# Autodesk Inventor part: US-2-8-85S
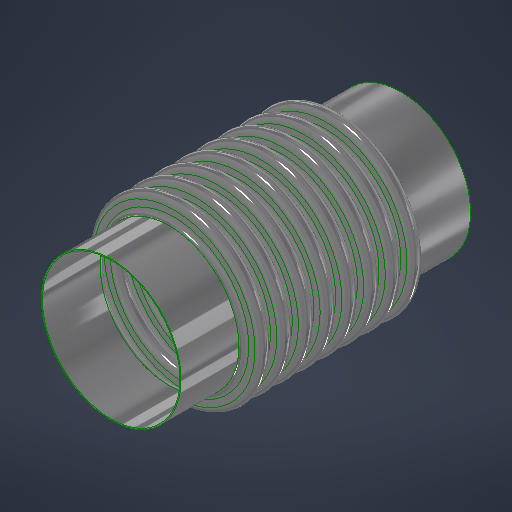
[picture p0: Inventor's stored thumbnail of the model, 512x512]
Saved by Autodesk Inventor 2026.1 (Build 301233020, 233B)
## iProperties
Created: 2026-07
Part Number: US-2-8-85S
Project: =STOCK BELLOWS: <Stock Number><SFILL>
Material: ASTM A240-304
Description: =STOCK BELLOWS: <Stock Number>, <SID_> I.D., <SOD_> O.D., <SPLY_> PLY, <Category>, <SNET_CONS> CONS.<PITCH_><STANGENT_> TANGENT<SFILL>
Document SubType Name: Sheet Metal
Designer: LC
Stock Number: U.S-2-8-85S
Surface Area: 659.127 cm^2
Volume: 56.61 cm^3
Sheet Metal Rule: Default
Appearance: STAINLESS STEEL
Category: 26 GA (0.018 THICK)
RuleStatus: InUse
Author: LC
Keywords: 20 GA (0.036 THICK)
NET_TUBE: 3.428
COUNTER: 1.500
PBAR: 1.214
PSET: 5.356
PLY: 2
CONS: 2
THK: 0.036
ID: 4.500
OD: 5.500
CONS_: 2
TANGENT: 0.500
PITCH: 0.375
BELLOWS_UPSET: 0.000
NET_CONS: 2
S_CONS: 0
Description_Units: 0
ID_M: 114.30 mm
OD_M: 139.70 mm
THK_M: 0.91 mm
ID_U: 4.500 in
OD_U: 5.500 in
THK_U: 0.036 in
TANGENT2: 0.500
d79: 1.000
d82: 1.000
d83: 26.000
d84: 24.000
d80: 2.571
d81: 10
SID: 2.375
SCONS_: 8
SPITCH: 0.250
SBELLOWS_UPSET: 0.000
SNET_CONS: 8
SS_CONS: 0
SCONS: 8
d174: 8
d177: 0.018
d178: 2.375
d179: 3.000
d180: 0.375
d181: 1.000
d182: 0.000
d190: 8
d191: 1
d192: 1
d193: 8
d194: 0
PART_NUMBER: U.S-2-8-85S
PRESSURE: 85
SIZE: 2.00
STANGENT_: 1.000
d214: 8
d217: 0.030
d218: 6.625
d219: 8.125
d220: 0.500
d221: 1.000
d222: 0.000
d230: 8
d231: 1
d232: 1
d233: 8
d234: 0
STANGENT: 4.000
SPLY_: 1
STHK_: 0.018
SID_: 2.375
SOD_: 3.000
SPITCH_: 0.375
STANGENT__: 1.000
SBELLOWS_UPSET_: 0.000
SDIFF_TAN: 1.000
TAN_TO_TAN: 0.750 in
d252: 2
d275: 2
d287: 0.050
d289: 0.500
d290: 0.000
d263: 2
d265: 1
d268: 2
d269: 0
d286: 2
d288: 1
d291: 2
d292: 0
SOD_NECK: 2 7/16
CFILL: .
SFILL: .
PITCH_: =, <SPITCH_> PITCH,
SREROLL: 0.750
MATTABLE: 20 GA (0.036 THICK)
MESH: ,
CSECT: 2
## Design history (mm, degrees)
sketch "Sketch2"
  geometry: L1 (0, -183.595)-(0, 600.956) reference; L2 (58.979, 0)-(57.15, 0); L3 (60.446, -1.467)-(66.554, -1.467); L4 (60.446, -3.296)-(66.554, -3.296); L5 (66.554, -8.058)-(60.446, -8.058); L6 (66.554, -6.229)-(60.446, -6.229); L7 (58.979, -9.525)-(57.15, -9.525); L8 (60.446, 0)-(60.446, -9.525); L9 (66.554, -4.762)-(69.85, -4.763); L10 (57.15, 0)-(57.15, -9.525); L11 (20.376, 102.841)-(20.376, 101.926); L12 (58.262, 488.877)-(58.262, 349.177); L13 (58.262, 479.352)-(58.262, 339.652); L14 (93.133, -58.817)-(93.133, -71.517); L15 (118.746, -66.401)-(118.746, -66.401); L16 (66.554, -6.229)-(66.554, -8.058); L17 (60.446, -6.229)-(60.446, -8.058); L18 (60.446, -7.144)-(66.554, -7.144); L19 (69.85, 0)-(69.85, -9.525); L20 (-66.554, -6.229)-(-66.554, -8.058); L21 (-66.554, -1.467)-(-60.446, -1.467); L22 (-66.554, -3.296)-(-60.446, -3.296); L23 (-60.446, -6.229)-(-66.554, -6.229); L24 (-66.554, -7.144)-(-60.446, -7.144); L25 (-60.446, -8.058)-(-66.554, -8.058); L26 (-60.446, -6.229)-(-60.446, -8.058); L27 (-57.15, -2.522)-(-57.15, -12.047); L28 (-60.446, -4.763)-(-57.15, -4.763); L29 (-66.554, 3.828)-(-66.554, -9.525); L30 (-68.021, 0)-(-69.85, 0); L31 (-69.85, 0)-(-69.85, -9.525); L32 (-68.021, -9.525)-(-69.85, -9.525); A1 r 1.467 centre (60.446, 0) between (58.979, 0) and (60.446, -1.467); A2 r 3.296 centre (60.446, 0) between (57.15, 0) and (60.446, -3.296); A3 r 3.296 centre (66.554, -4.762) between (66.554, -8.058) and (66.554, -1.467); A4 r 1.467 centre (66.554, -4.762) between (66.554, -6.229) and (66.554, -3.296); A5 r 1.467 centre (60.446, -9.525) between (60.446, -8.058) and (58.979, -9.525); A6 r 3.296 centre (60.446, -9.525) between (60.446, -6.229) and (57.15, -9.525); A7 r 2.381 centre (66.554, -4.762) between (66.554, -7.144) and (68.936, -4.762); A8 r 2.381 centre (60.446, -9.525) between (60.446, -7.144) and (58.064, -9.525); A9 r 1.467 centre (-66.554, -9.525) between (-66.554, -8.058) and (-68.021, -9.525); A10 r 1.467 centre (-60.446, -4.763) between (-60.446, -6.229) and (-60.446, -3.296); A11 r 2.381 centre (-60.446, -4.763) between (-60.446, -7.144) and (-58.064, -4.763); A12 r 3.296 centre (-60.446, -4.763) between (-60.446, -8.058) and (-60.446, -1.467); A13 r 2.381 centre (-66.554, -9.525) between (-66.554, -7.144) and (-68.936, -9.525); A14 r 3.296 centre (-66.554, -9.525) between (-66.554, -6.229) and (-69.85, -9.525); A15 r 1.467 centre (-66.554, 0) between (-68.021, 0) and (-66.554, -1.467); A16 r 3.296 centre (-66.554, 0) between (-69.85, 0) and (-66.554, -3.296); 10 further points
  constraints: 62 end point, 38 point on circle, 20 tangent, 16 centre point, 12 parallel, 9 midpoint, 7 vertical, 6 coincident, 6 concentric, 6 point on line, 4 equal radius, 4 perpendicular, 3 horizontal, 1 collinear, 1 horizontal alignment, 10 other
  dimensions: "THK" = 0.9144 distance of L11.start L11.end; "ID" = 114.3 distance of L11.end point (20.376, -12.374); "OD" = 139.7 distance of L12.start L12.end; "PITCH" = 9.525 distance of L12.start L13.start; "TANGENT" = 12.7 distance of L14.start L14.end; "BELLOWS_UPSET" = 0 distance of L15.start L15.end; "d43" = 114.3 diameter of L10 L1 (= ID); "d44" = 139.7 diameter of L9.end L1 (= OD); "d45" = 1.8288 distance between parallel lines of L5 L6 (computed from THK, PLY); "d46" = 3.29565 radius of A3 (computed from PITCH, THK, PLY); "UPSET_PITCH" = 9.525 distance of L2.end L7.end (derived); "SIDEWALL_ANGLE" = 0 deg angle of L3 L9 (derived); "CON_GAP" = 2.9337 distance of point (60.446, -6.229) point (60.446, -3.296) (derived); "TAN1" = 3.74046 dimension on A8 (derived); "TAN2" = 3.74046 dimension on A7 (derived); "LEG1" = 6.1087 distance of L18.start L18.end (derived); "d278" = 1.8288 distance between parallel lines of L25 L23 (derived); "d279" = 3.29565 radius of A12 (derived); "d280" = 9.525 distance of L30.end L31.end (derived); "d281" = 360 deg dimension on L21 L28 (derived); "d282" = 2.9337 distance of point (-66.554, -6.229) point (-66.554, -3.296) (derived); "d283" = 3.74046 dimension on A13 (derived); "d284" = 3.74046 dimension on A11 (derived); "d285" = 6.1087 distance of L24.start L24.end (derived); "d293" = 114.3 diameter of L27 L1 (derived); "d294" = 139.7 diameter of L31 L1 (derived)
  node "Sketch Rectangular Pattern1" dims "d31" = 25.4, "ID" = 114.3
  node "Sketch Rectangular Pattern2" dims "d39" = 25.4, "PITCH" = 9.525
revolve "CONS" stored, may be unused: angle "d48" = 90 deg
node "BELLOW MIDPLANE"
pattern_linear "Rectangular Pattern2" dims "d52" = 9.525 (= UPSET_PITCH)
sketch "Sketch5"
  geometry: C1 r 58.979 at (0, 0) reference; C2 r 57.15 at (0, 0) reference
extrude "TANGENT" new body sketch "Sketch5" distance "d53" = 12.7 (= TANGENT); taper "d54" = 0 deg
revolve "SAMETAN" stored, may be unused: angle "d65" = 90 deg
revolve "DIFFTAN" stored, may be unused: angle "d70" = 90 deg
sketch "Sketch9"
  geometry: L1 (58.391, 0)-(-58.391, 0) reference; L2 (0, -17.78)-(0, 17.78) reference; L3 (41.708, 0)-(-41.708, 0); L4 (41.708, -11.906)-(41.708, 11.906); L5 (29.008, -11.906)-(29.008, 11.906); L6 (15.418, 11.906)-(15.418, -11.906); L7 (-29.008, -11.906)-(-29.008, 11.906); L8 (-41.708, -11.906)-(-41.708, 11.906); L9 (40.914, -11.906)-(40.914, 11.906); L10 (41.708, -11.906)-(40.914, -11.906); L11 (41.708, 11.906)-(40.914, 11.906); L12 (15.815, 11.906)-(15.022, 11.906); L13 (15.022, 11.906)-(15.022, -11.906); L14 (15.022, -11.906)-(15.815, -11.906); L15 (15.815, -11.906)-(15.815, 11.906); L16 (-15.815, 11.906)-(-15.815, -11.906); L17 (-15.418, 11.906)-(-15.418, -11.906); L18 (-15.815, -11.906)-(-15.022, -11.906); L19 (-15.022, -11.906)-(-15.022, 11.906); L20 (-15.022, 11.906)-(-15.815, 11.906); L21 (-41.708, -11.906)-(-40.914, -11.906); L22 (-40.914, -11.906)-(-40.914, 11.906); L23 (-40.914, 11.906)-(-41.708, 11.906); L24 (-41.708, 11.906)-(-41.708, -11.906); L25 (41.708, -0.397)-(-41.708, -0.397); L26 (-41.708, -0.397)-(-41.708, 0.397); L27 (-41.708, 0.397)-(41.708, 0.397); L28 (41.708, 0.397)-(41.708, -0.397); L29 (-41.708, 11.906)-(41.708, 11.906); L30 (41.708, 11.906)-(41.708, 12.7); L31 (41.708, 12.7)-(-41.708, 12.7); L32 (-41.708, 12.7)-(-41.708, 11.906); L33 (41.708, -11.906)-(-41.708, -11.906); L34 (-41.708, -11.906)-(-41.708, -12.7); L35 (-41.708, -12.7)-(41.708, -12.7); L36 (41.708, -12.7)-(41.708, -11.906); 30 further points
  constraints: 68 end point, 13 midpoint, 13 parallel, 8 horizontal, 7 perpendicular, 6 equal length, 3 point on line, 2 vertical, 14 other
  dimensions: "d115" = 23.8125 distance of L4.start L4.end (derived); "d116" = 12.7 distance between parallel lines of L4 L5 (derived); "d117" = 13.58962 distance between parallel lines of L5 L6 (derived); "d125" = 44.42645 distance between parallel lines of L7 L6 (derived); "d127" = 12.7 distance between parallel lines of L8 L7 (derived); "d128" = 26.28962 distance between parallel lines of L6 L4 (derived); "d130" = 83.41607 distance between parallel lines of L8 L4 (derived); "RULER_THK" = 0.79375 distance between parallel lines of L4 L9; "d135" = 0.79375 distance of L13.end L14.end (derived); "d138" = 30.83684 distance of L13.end L16.end (derived); "d143" = 0.79375 distance of L22.end L8.end (derived); "d144" = 0.79375 distance between parallel lines of L27 L25 (derived)
extrude "RULER" join sketch "Sketch9" distance "d149" = 0.79375 (derived); taper "d150" = 0 deg
extrude "BARS" join sketch "Sketch9" distance "d151" = 0.79375 (derived); taper "d152" = 0 deg
pattern_linear "Rectangular Pattern4" dims "d155" = 30.83684 (derived)
sketch "Sketch13"
  geometry: L1 (93.149, -52.467)-(93.149, -77.867); L2 (30.62, 0)-(30.162, 0); L3 (30.62, -9.525)-(30.162, -9.525); L4 (35.49, -7.372)-(32.772, -7.372); L5 (35.49, -6.915)-(32.772, -6.915); L6 (35.49, -4.763)-(38.1, -4.763); L7 (32.772, -2.153)-(35.49, -2.153); L8 (32.772, 0)-(32.772, -9.525); L9 (30.162, 0)-(30.162, -9.525); L10 (58.254, -373.664)-(58.254, -449.864); L11 (58.254, -383.189)-(58.254, -459.389); L12 (58.254, -402.239)-(58.254, -478.439); L13 (58.254, -411.764)-(58.254, -487.964); L14 (58.254, -421.289)-(58.254, -497.489); L15 (58.254, -430.814)-(58.254, -507.014); L16 (58.254, -440.339)-(58.254, -516.539); L17 (58.254, -392.714)-(58.254, -468.914); L18 (20.376, 102.383)-(20.376, 101.926); L19 (32.772, -2.61)-(35.49, -2.61); L20 (0, -696.265)-(0, 235.847) reference; L21 (-23.752, 0)-(142.514, 0) reference; A1 r 2.153 centre (32.772, 0) between (30.62, 0) and (32.772, -2.153); A2 r 2.153 centre (32.772, -9.525) between (32.772, -7.372) and (30.62, -9.525); A3 r 2.61 centre (32.772, -9.525) between (32.772, -6.915) and (30.162, -9.525); A4 r 2.153 centre (35.49, -4.763) between (35.49, -6.915) and (35.49, -2.61); A5 r 2.61 centre (35.49, -4.763) between (35.49, -7.372) and (35.49, -2.153); A6 r 2.61 centre (32.772, 0) between (30.162, 0) and (32.772, -2.61); 6 further points; 1 other entity
  constraints: 38 end point, 15 point on circle, 9 tangent, 6 centre point, 6 parallel, 5 vertical alignment, 4 point on line, 4 vertical, 3 coincident, 3 concentric, 2 collinear, 2 equal radius, 1 horizontal, 1 perpendicular, 23 other
  dimensions: "SBELLOWS_UPSET_" = 0 distance of point (118.762, -66.401) point (118.762, -66.401); "STOTAL_THK_BELLOW__" = 0.4572 distance between parallel lines of L4 L5 (derived); "d224" = 2.60985 radius of A5 (derived); "d225" = 9.525 distance of L2.end L3.end (derived); "SSIDEWALL_ANGLE_" = 360 deg dimension on L7 L6 (derived); "SSCON_GAP_" = 4.3053 distance of point (32.772, -6.915) point (32.772, -2.61) (derived); "d235" = 60.325 diameter of L9 L20 (derived); "d236" = 76.2 diameter of L6.end L20 (derived)
  node "Sketch Rectangular Pattern4" dims "d228" = 25.4
  node "Sketch Rectangular Pattern5" dims "d229" = 25.4
revolve "SBELLOW" stored, may be unused: angle "d197" = 90 deg
pattern_linear "Rectangular Pattern5" dims "d204" = 9.525 (derived)
revolve "STANGENT" stored, may be unused: angle "d240" = 90 deg
revolve "SSAMETAN" stored, may be unused: angle "d241" = 90 deg
revolve "SDIFFTAN" stored, may be unused: angle "d246" = 90 deg
revolve "INVCON" stored, may be unused: angle "d295" = 90 deg
pattern_linear "Rectangular Pattern6" dims "d298" = 9.525 (derived)
revolve "INVTANGENT" stored, may be unused: angle "d302" = 90 deg
revolve "INVSAMETAN" stored, may be unused: angle "d307" = 90 deg
revolve "INVDIFFTAN" stored, may be unused: angle "d312" = 90 deg
sketch "ID BELLOW MOUNT CALC"
  geometry: L1 (44.45, 0)-(38.1, 0); L2 (38.1, 0)-(38.1, 12.7); L3 (38.1, 12.7)-(44.45, 12.7); L4 (44.45, 12.7)-(44.45, 0); L5 (36.513, 12.7)-(34.684, 12.7); L6 (34.684, 12.7)-(34.684, 0); L7 (34.684, 0)-(36.513, 0); L8 (36.513, 0)-(36.513, 12.7); L9 (0, -2.54)-(0, 15.24) reference; L10 (-8.89, 0)-(53.34, 0) reference; 1 further point
  constraints: 16 end point, 5 parallel, 2 collinear, 2 horizontal, 2 perpendicular
  dimensions: "d314" = 12.7 distance of L5.end L6.end (derived); "d315" = 1.8288 distance of L5.start L5.end (derived); "IG" = 1.5875 distance between parallel lines of L2 L8; "PIPE_OD" = 88.9 diameter of L4 L9; "PIPE_WALL" = 6.35 distance of L2.end L3.end; "ID_MT_BELLOW" = 69.3674 diameter of L6 L9 (derived)
revolve "CFILL" stored, may be unused: angle "d320" = 90 deg
pattern_linear "Rectangular Pattern7" dims "d323" = 9.525 (derived)
revolve "SFILL" stored, may be unused: angle "d324" = 90 deg
pattern_linear "Rectangular Pattern8" dims "d327" = 9.525 (derived)
node "STOCK BELLOW MIDPLANE"
sketch "Sketch21"
  geometry: L1 (0, -100.013)-(0, 100.013) reference; L2 (-100.013, 0)-(100.013, 0) reference; L3 (-0.099, 71.437)-(0.099, 71.437); L4 (0.099, 71.437)-(0.099, 55.562); L5 (0.099, 55.562)-(-0.099, 55.562); L6 (-0.099, 55.562)-(-0.099, 71.437); C1 r 55.562 at (0, 0); C2 r 71.437 at (0, 0); 3 further points
  constraints: 8 end point, 2 centre point, 2 coincident, 2 parallel, 2 tangent, 1 horizontal, 1 perpendicular, 1 other
  dimensions: "d329" = 111.125 diameter of C1 (derived); "d330" = 142.875 diameter of C2 (derived); "d331" = 0.19844 distance of L3.start L3.end
extrude "CLAMSHELL" cut sketch "Sketch21" extent not by distance; stored distance "d332" = 0; taper "d333" = 0 deg
pattern_circular "Circular Pattern1" dims angle "d335" = 180 deg (derived)
node "BELLOW"
sketch "Sketch6"
  geometry: L1 (-19.05, 58.979)-(-6.35, 58.979); L2 (-6.35, 58.979)-(-6.35, 57.15); L3 (-6.35, 57.15)-(-19.05, 57.15); L4 (-19.05, 57.15)-(-19.05, 58.979); L5 (2.54, 0)-(-59.69, 0) reference; L6 (-38.1, -108.388)-(-38.1, 156.601) reference; 1 further point
  constraints: 8 end point, 2 parallel, 1 horizontal, 1 perpendicular
  dimensions: "d61" = 12.7 distance of L2.end L3.end (derived); "d62" = 1.8288 distance of L1.end L2.end (derived); "d63" = 114.3 diameter of L3 L5 (derived); "d64" = 19.05 distance between parallel lines of L4 L6 (derived)
sketch "Sketch12"
  geometry: 1 further point
sketch "Sketch14"
  geometry: L1 (-25.4, 30.62)-(0, 30.62); L2 (0, 30.62)-(0, 30.162); L3 (0, 30.162)-(-25.4, 30.162); L4 (-25.4, 30.162)-(-25.4, 30.62); L5 (5.08, 0)-(-30.48, 0) reference; L6 (0, -11.582)-(0, 69.494) reference; 1 further point
  constraints: 8 end point, 2 parallel, 1 collinear, 1 horizontal, 1 perpendicular
  dimensions: "d237" = 0.4572 distance of L3.end L1.start (derived); "d238" = 60.325 diameter of L3 L5 (derived); "d239" = 25.4 distance of L1.start L1.end (derived); "SOD_NECK" = 61.2394 diameter of L1 L5 (derived)
sketch "Sketch15"
  geometry: L1 (-11.582, 0)-(69.494, 0) reference; L2 (30.163, -76.2)-(30.62, -76.2); L3 (30.62, -76.2)-(30.62, -101.6); L4 (30.62, -101.6)-(30.163, -101.6); L5 (30.163, -101.6)-(30.163, -76.2); L6 (0, -124.46)-(0, 35.56) reference; 1 further point
  constraints: 8 end point, 2 parallel, 1 horizontal, 1 perpendicular
  dimensions: "d205" = 25.4 distance of L4.end L2.start (derived); "d206" = 0.4572 distance of L3.end L4.end (derived); "d207" = 60.325 diameter of L5 L6 (derived); "d208" = 76.2 distance between parallel lines of L1 L2 (derived)
node "TANGENT_"
node "SAME_TAN"
sketch "Sketch8"
  geometry: L1 (58.979, -19.05)-(57.15, -19.05); L2 (57.15, -19.05)-(57.15, -31.75); L3 (57.15, -31.75)-(58.979, -31.75); L4 (58.979, -31.75)-(58.979, -19.05); L5 (0, -40.64)-(0, 21.59) reference; L6 (-108.388, 0)-(156.601, 0) reference; 1 further point
  constraints: 8 end point, 2 parallel, 1 horizontal, 1 perpendicular
  dimensions: "d66" = 114.3 diameter of L2 L5 (derived); "TOTAL_THK_BELLOW" = 1.8288 distance of L2.end L3.end (derived); "d68" = 19.05 distance between parallel lines of L1 L6 (derived); "d69" = 12.7 distance of L1.end L2.end (derived)
node "DIFF_TAN"
node "Sketch Rectangular Pattern3" dims "d138" = 30.83684 (derived), "d141" = 25.4
node "SBELLOW_"
node "STANGENT_"
node "SSAME_TAN"
sketch "Sketch16"
  geometry: L1 (30.62, -76.2)-(30.163, -76.2); L2 (30.163, -76.2)-(30.163, -101.6); L3 (30.163, -101.6)-(30.62, -101.6); L4 (30.62, -101.6)-(30.62, -76.2); L5 (0, -124.46)-(0, 35.56) reference; L6 (-11.582, 0)-(69.494, 0) reference; 1 further point
  constraints: 8 end point, 2 parallel, 1 horizontal, 1 perpendicular
  dimensions: "SDIFF_TAN" = 25.4 distance of L3.end L1.start; "d243" = 0.4572 distance of L2.end L3.end (derived); "d244" = 76.2 distance between parallel lines of L1 L6 (derived); "d245" = 60.325 diameter of L2 L5 (derived)
node "SDIFF_TAN"
body "Solid15"
sketch "Sketch17"
  geometry: L1 (69.85, 12.7)-(68.021, 12.7); L2 (68.021, 12.7)-(68.021, 0); L3 (68.021, 0)-(69.85, 0); L4 (69.85, 0)-(69.85, 12.7); L5 (0, -2.54)-(0, 15.24) reference; L6 (-13.97, 0)-(83.82, 0) reference; 2 further points
  constraints: 8 end point, 2 parallel, 1 horizontal, 1 midpoint, 1 perpendicular, 1 point on line
  dimensions: "INVTANGENT" = 12.7 distance of L3.end L1.start (derived); "d300" = 1.8288 distance of L1.start L1.end (derived); "d301" = 139.7 diameter of L4 L5 (derived)
body "Solid16"
sketch "Sketch18"
  geometry: L1 (69.85, -19.05)-(68.021, -19.05); L2 (68.021, -19.05)-(68.021, -31.75); L3 (68.021, -31.75)-(69.85, -31.75); L4 (69.85, -31.75)-(69.85, -19.05); L5 (-13.97, 0)-(83.82, 0) reference; L6 (0, -40.64)-(0, 21.59) reference; 1 further point
  constraints: 8 end point, 2 parallel, 1 horizontal, 1 perpendicular
  dimensions: "d303" = 19.05 distance between parallel lines of L1 L5 (derived); "d304" = 12.7 distance of L3.end L1.start (derived); "d305" = 1.8288 distance of L2.end L3.end (derived); "d306" = 139.7 diameter of L4 L6 (derived)
body "Solid17"
sketch "Sketch19"
  geometry: L1 (69.85, -19.05)-(68.021, -19.05); L2 (68.021, -19.05)-(68.021, -31.75); L3 (68.021, -31.75)-(69.85, -31.75); L4 (69.85, -31.75)-(69.85, -19.05); L5 (0, -40.64)-(0, 21.59) reference; L6 (-13.97, 0)-(83.82, 0) reference; 1 further point
  constraints: 8 end point, 2 parallel, 1 horizontal, 1 perpendicular
  dimensions: "d308" = 12.7 distance of L1.end L2.end (derived); "d309" = 139.7 diameter of L4 L5 (derived); "d310" = 1.8288 distance of L2.end L3.end (derived); "d311" = 19.05 distance between parallel lines of L1 L6 (derived)
body "Solid18"
body "Solid19"
body "Solid20"
other parameters: "BMPL" = -38.1, "PSET" = 136.0424 (computed from OD, THK, PLY) [user parameter], "PBAR" = 30.83684 (= 0.570796 x PITCH + OD - ID) [user parameter; used in 1 equation term], "COUNTER" = 15 [user parameter], "NET_TUBE" = 87.07367 (computed from CONS_, PBAR, TANGENT) [user parameter], "S_CONS" = 0 [user parameter; used in 1 equation term], "ID_M" = 114.3 (= ID) [user parameter], "OD_M" = 139.7 (= OD) [user parameter], "THK_M" = 0.9144 (= THK) [user parameter], "ID_U" = 114.3 (= ID) [user parameter], "OD_U" = 139.7 (= OD) [user parameter], "THK_U" = 0.9144 (= THK) [user parameter], "D_UNITS" = 0 [user parameter], "TANGENT2" = 12.7 [user parameter], "TAN_TO_TAN" = 19.05 [user parameter], "OD_NECK" = 117.9576 [user parameter], "d79" = 25.4, "d80" = 65.29823 [user parameter], "d82" = 25.4, "d83" = 660.4, "d84" = 609.6, "sa_0" = 4, "FRAME_THK" = 0.79375 [user parameter], "CON_FLAT" = 13.58962 [user parameter], "SID" = 60.325 [user parameter], "SPITCH" = 6.35 [user parameter], "STANGENT_" = 25.4 [user parameter], "SBELLOWS_UPSET" = 0 [user parameter], "SS_CONS" = 0 [user parameter], "STAN_TO_TAN_" = 76.2 [user parameter], "d100" = 0.4572 [user parameter], "d191" = 25.4 [user parameter], "d194" = 0 [user parameter], "STANGENT" = 101.6 [user parameter], "d234" = 0 [user parameter], "SUPSET_PITCH_" = 9.525 [user parameter], "d269" = 0 [user parameter], "d287" = 1.27, "d289" = 12.7, "d290" = 0, "d292" = 0 [user parameter], "Thickness" = 3.048 (derived), "KFactor" = 4.4, "BendRadius" = 3.048 (derived), "BendReliefWidth" = 3.048 (derived), "BendReliefDepth" = 1.524 (derived), "CornerReliefSize" = 12.192 (derived), "SeamGap" = 0.00508, "MinimumRemnant" = 6.096 (derived), "TransitionRadius" = 3.048 (derived), "JacobiRadiusSize" = 3.048 (derived), "GapSize" = 3.048 (derived), "SREROLL" = 19.05 [user parameter], "CUR_STK_PITCH" = 9.525 [user parameter], "d328" = -38.1 (derived), "CSECTDEG" = 180 deg [user parameter]
